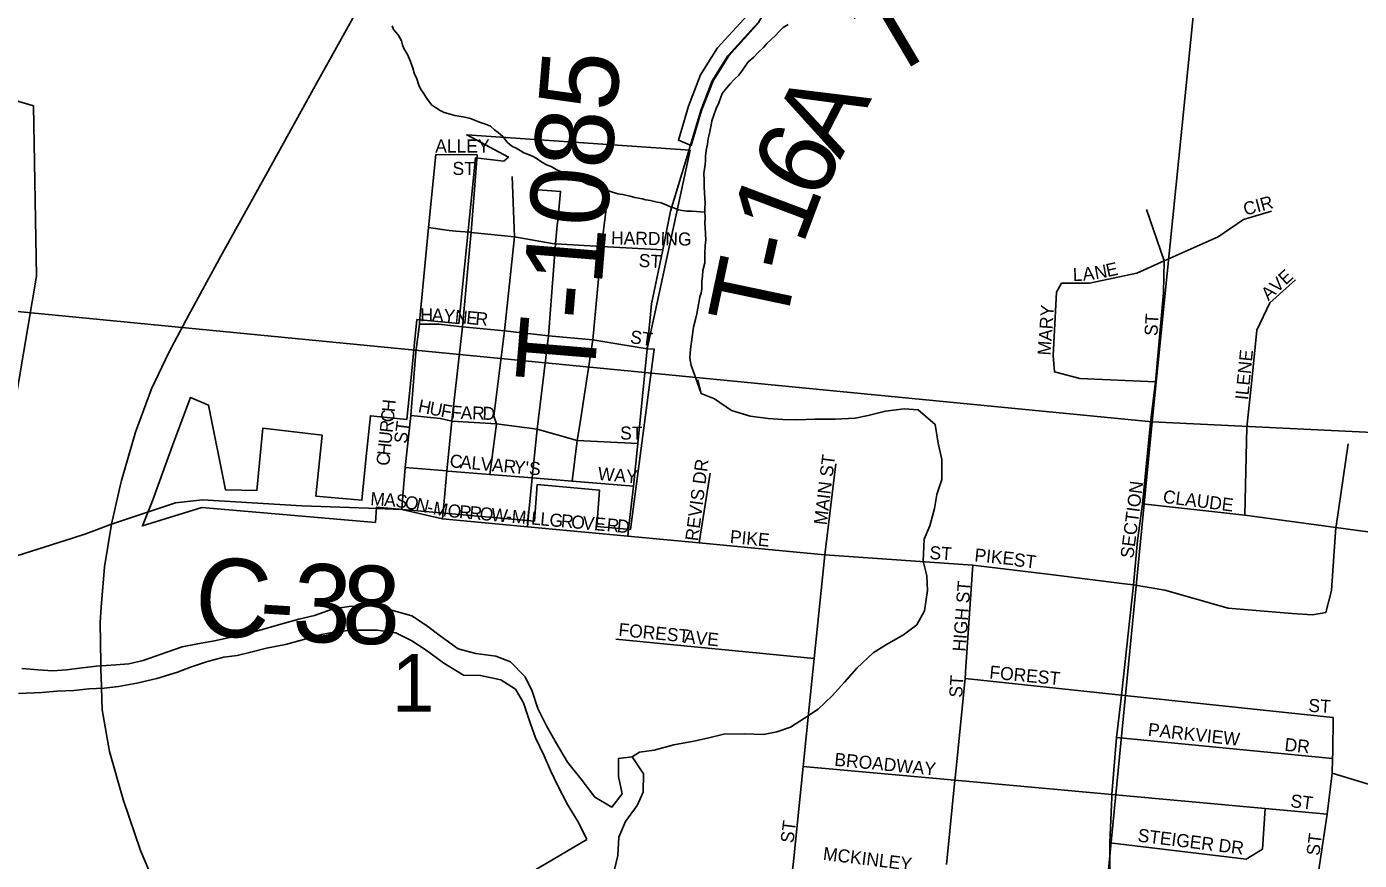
# Model space of a CAD drawing. Extents: x 0 to 34, y -4 to 22.
# Drawn here: x 5.062 to 5.742, y 17.725 to 18.151 of the extents above; entities that cross this region are included whole.
import ezdxf

# ---------------------------------------------------------------- set-up
doc = ezdxf.new("R2010")
doc.units = 0
for name, color, linetype in [('GM_X_City_Street', 7, 'Continuous'), ('GM_X_City_Street_Text', 7, 'Continuous'), ('GM_X_Corporation', 7, 'Continuous'), ('GM_X_County_Road', 7, 'Continuous'), ('GM_X_County_Road_Text', 7, 'Continuous'), ('GM_X_Minor_River', 7, 'Continuous'), ('GM_X_Section', 7, 'Continuous'), ('GM_X_Section_Text', 7, 'Continuous'), ('GM_X_State_Route', 7, 'Continuous'), ('GM_X_Township_Road', 7, 'Continuous'), ('GM_X_Township_Road_Text', 7, 'Continuous'), ('GM_X_Township_ROW', 7, 'Continuous'), ('GM_X_Township_Subdivision', 7, 'Continuous'), ('GM_X_Township_Subdivision_Text', 7, 'Continuous')]:
    doc.layers.add(name, color=color, linetype=linetype)

msp = doc.modelspace()

# ---------------------------------------------------------------- linework, layer by layer
at = {"layer": 'GM_X_City_Street'}
for points in [[(5.27062, 18.0859), (5.29176, 18.08574)], [(5.63136, 17.90479), (5.63174, 17.90741), (5.63574, 17.94878), (5.63841, 17.96979), (5.64241, 18.01517), (5.64275, 18.03151), (5.63374, 18.05787)], [(5.63841, 17.96979), (5.59971, 17.97147), (5.5867, 17.9748), (5.58603, 17.98314), (5.5877, 18.0155), (5.59037, 18.02017), (5.60465, 18.02018), (5.6288, 18.0252), (5.64275, 18.03151), (5.67035, 18.04379), (5.68336, 18.05263), (5.69761, 18.0569)], [(5.26689, 18.04859), (5.27746, 18.04703), (5.28092, 18.04675)], [(5.68508, 17.9467), (5.68512, 17.94811), (5.68778, 17.97213), (5.69012, 17.99615), (5.69679, 18.01016), (5.70981, 18.02184)], [(5.68401, 17.9016), (5.68508, 17.9467)], [(5.73064, 17.89595), (5.73683, 17.9381)], [(5.40523, 17.88742), (5.41078, 17.92313)], [(5.46943, 17.8814), (5.47503, 17.92779)], [(5.25323, 17.90455), (5.25382, 17.91153)], [(5.10485, 17.89711), (5.1182, 17.90151), (5.12485, 17.9037)], [(5.23627, 17.90518), (5.25323, 17.90455), (5.27401, 17.89971), (5.31747, 17.89564), (5.36866, 17.89085)], [(5.27401, 17.89971), (5.27467, 17.90687)], [(5.31747, 17.89564), (5.31822, 17.90326)], [(5.62066, 17.80666), (5.62103, 17.80968), (5.62707, 17.86604), (5.62907, 17.88873), (5.63136, 17.90479)], [(5.63174, 17.90741), (5.68401, 17.9016), (5.73055, 17.89534), (5.77956, 17.88875), (5.82697, 17.88237), (5.87075, 17.87648)], [(5.08493, 17.88989), (5.09184, 17.89207), (5.10485, 17.89711)], [(5.36866, 17.89085), (5.36945, 17.89762)], [(5.62252, 17.86661), (5.62707, 17.86604), (5.64308, 17.86337), (5.67544, 17.85403), (5.70813, 17.85136), (5.71848, 17.85069), (5.72537, 17.85198), (5.72826, 17.86315), (5.72951, 17.88072), (5.73055, 17.89534), (5.73064, 17.89595)], [(4.38714, 17.81483), (4.45287, 17.83314), (4.50971, 17.84877), (4.57933, 17.86961), (4.62669, 17.88287), (4.64942, 17.88287), (4.86174, 17.86416), (4.91107, 17.85815), (4.95215, 17.8548), (4.96722, 17.85635), (4.99636, 17.86184), (5.08493, 17.88989)], [(5.36866, 17.89085), (5.40523, 17.88742), (5.44783, 17.88343)], [(5.44783, 17.88343), (5.46943, 17.8814), (5.545, 17.87605), (5.54484, 17.87376)], [(5.46142, 17.80356), (5.46397, 17.82832), (5.46943, 17.8814)], [(5.54484, 17.87376), (5.54151, 17.8242)], [(5.545, 17.87605), (5.5847, 17.87138), (5.62252, 17.86661)], [(5.36258, 17.83827), (5.46397, 17.82832)], [(5.54151, 17.8242), (5.54111, 17.81819), (5.62103, 17.80968), (5.72564, 17.79855)], [(5.53601, 17.76749), (5.5365, 17.77239), (5.54111, 17.81819)], [(5.61599, 17.75753), (5.61605, 17.75885), (5.61839, 17.78798), (5.62066, 17.80666)], [(5.44097, 17.64142), (5.44324, 17.64787), (5.44562, 17.66039), (5.44744, 17.67536), (5.45259, 17.71772), (5.45331, 17.72468), (5.4583, 17.77321), (5.46142, 17.80356)], [(5.72564, 17.79855), (5.72919, 17.79817), (5.72886, 17.78046)], [(5.61839, 17.78798), (5.7288, 17.77737)], [(5.72886, 17.78046), (5.7288, 17.77737), (5.72865, 17.76986), (5.76503, 17.75881), (5.78948, 17.75139), (5.81441, 17.74382), (5.82715, 17.73996)], [(5.4583, 17.77321), (5.5358, 17.76615)], [(5.53155, 17.72313), (5.5319, 17.7266), (5.53587, 17.76615), (5.53601, 17.76749)], [(5.5358, 17.76615), (5.53587, 17.76615), (5.61605, 17.75885), (5.69429, 17.75172), (5.72603, 17.74883)], [(5.70634, 17.59125), (5.7183, 17.69768), (5.72603, 17.74883), (5.72865, 17.76986)], [(5.61523, 17.70819), (5.61505, 17.73426), (5.61599, 17.75753)], [(5.61505, 17.73426), (5.68463, 17.72584), (5.69303, 17.73102), (5.69429, 17.75172)]]:
    msp.add_lwpolyline(points, dxfattribs=at)
at = {"layer": 'GM_X_Corporation'}
for points in [[(5.42987, 18.15717), (5.41459, 18.14035), (5.40585, 18.12661), (5.39971, 18.11054), (5.39455, 18.09331), (5.40111, 18.09053), (5.40646, 18.10839), (5.41227, 18.1236), (5.42034, 18.13629), (5.43595, 18.15363)], [(5.05329, 17.94512), (5.06658, 18.02376), (5.06502, 18.11083), (4.93029, 18.15055)], [(5.05329, 17.94512), (5.06658, 18.02376), (5.06502, 18.11083), (4.93029, 18.15055)]]:
    msp.add_lwpolyline(points, dxfattribs=at)
msp.add_lwpolyline([(5.23974, 17.89786), (5.24029, 17.90568), (5.32104, 17.89862), (5.32235, 17.91724), (5.35423, 17.91445), (5.35292, 17.89583), (5.37002, 17.89433), (5.38224, 17.98644), (5.37863, 17.98662), (5.40058, 18.08807), (5.28645, 18.09596), (5.30775, 18.08462), (5.30546, 18.08258), (5.29089, 18.0842), (5.2824, 17.99957), (5.26095, 18.0016), (5.26059, 17.99798), (5.25978, 17.98989), (5.25851, 17.97709), (5.25587, 17.95052), (5.2372, 17.95245), (5.23513, 17.93167), (5.23291, 17.90929), (5.2094, 17.91136), (5.21251, 17.9425), (5.18229, 17.9461), (5.17917, 17.91422), (5.16323, 17.91457), (5.15457, 17.95788), (5.14536, 17.9618), (5.13672, 17.93912), (5.12593, 17.9089), (5.12073, 17.89613), (5.15109, 17.90549)], close=True, dxfattribs=at)
at = {"layer": 'GM_X_County_Road'}
msp.add_lwpolyline([(5.12485, 17.9037), (5.13755, 17.90789), (5.15148, 17.9095), (5.20221, 17.90644), (5.23627, 17.90518)], dxfattribs=at)
at = {"layer": 'GM_X_Minor_River'}
for points in [[(5.40805, 18.05647), (5.40164, 18.05694), (5.39896, 18.05702), (5.39656, 18.05736), (5.3947, 18.05769), (5.39258, 18.05855), (5.39046, 18.05915), (5.38861, 18.06001), (5.3857, 18.06117), (5.38304, 18.06179), (5.38039, 18.0624), (5.37799, 18.06274), (5.37613, 18.06334), (5.37427, 18.06366), (5.3724, 18.06398), (5.37001, 18.06459), (5.36602, 18.06552), (5.36362, 18.06586), (5.35991, 18.06704), (5.35699, 18.06793), (5.35381, 18.06883), (5.35117, 18.06998), (5.34851, 18.0706), (5.34508, 18.07231), (5.34165, 18.07375), (5.33743, 18.07602), (5.33426, 18.07718), (5.33215, 18.07832), (5.32952, 18.07973), (5.32714, 18.08061), (5.32425, 18.0823), (5.32242, 18.08369), (5.32031, 18.08483), (5.31794, 18.08597), (5.31556, 18.08684), (5.31372, 18.08797), (5.31161, 18.0891), (5.30951, 18.09024), (5.30716, 18.09218), (5.30485, 18.09519), (5.3025, 18.09713), (5.30067, 18.09852), (5.29859, 18.10046), (5.29594, 18.10134), (5.29303, 18.1025), (5.29038, 18.10338), (5.28827, 18.10425), (5.28455, 18.10516), (5.28242, 18.1055), (5.28028, 18.10583), (5.27789, 18.10644), (5.27497, 18.10733), (5.27287, 18.10846), (5.27103, 18.10959), (5.26841, 18.11127), (5.2661, 18.11455), (5.26432, 18.11728), (5.26278, 18.11946), (5.26204, 18.12135), (5.26083, 18.12513), (5.25982, 18.12703), (5.25885, 18.13), (5.25762, 18.13351), (5.25613, 18.13703), (5.25435, 18.14002), (5.25361, 18.14192), (5.25315, 18.14407), (5.25137, 18.14706), (5.24905, 18.1498), (5.24831, 18.1517)], [(5.40442, 17.97083), (5.4062, 17.96384), (5.40216, 17.97544), (5.40118, 17.97815), (5.4007, 17.98003), (5.4005, 17.98191), (5.40059, 17.98458), (5.40096, 17.98777), (5.40131, 17.99016), (5.40166, 17.99282), (5.40236, 17.99761), (5.40329, 18.00159), (5.40392, 18.00451), (5.40456, 18.00743), (5.40521, 18.01115), (5.40555, 18.01327), (5.40615, 18.01512), (5.40649, 18.01725), (5.40655, 18.01912), (5.40662, 18.02126), (5.40697, 18.02365), (5.40706, 18.02658), (5.408, 18.03056), (5.40808, 18.03296), (5.40816, 18.03536), (5.40829, 18.03937), (5.40866, 18.0423), (5.40849, 18.04524), (5.40833, 18.04872), (5.40813, 18.05059), (5.40822, 18.05353), (5.40805, 18.05647), (5.40813, 18.05887), (5.40819, 18.06074), (5.40802, 18.06369), (5.40784, 18.06636), (5.40768, 18.06957), (5.40779, 18.07278), (5.40763, 18.07625), (5.40798, 18.07865), (5.40832, 18.08077), (5.40839, 18.08291), (5.40846, 18.08504), (5.40883, 18.08797), (5.40947, 18.09116), (5.40983, 18.09408), (5.41045, 18.09674), (5.41078, 18.0986), (5.4114, 18.10098), (5.41174, 18.10311), (5.41264, 18.10602), (5.41382, 18.10946), (5.41526, 18.11235), (5.41614, 18.11473), (5.41702, 18.1171), (5.41842, 18.11893), (5.42094, 18.12206), (5.42316, 18.12439), (5.42537, 18.12646), (5.42733, 18.12907), (5.43015, 18.13326), (5.43317, 18.13557), (5.43512, 18.13792), (5.43816, 18.14076), (5.43983, 18.14258), (5.44204, 18.14465), (5.44426, 18.14672), (5.44592, 18.14854), (5.44814, 18.15087), (5.45061, 18.1524)], [(5.37089, 17.77816), (5.3747, 17.78047), (5.38222, 17.78161), (5.39219, 17.7843), (5.40241, 17.78619), (5.40941, 17.78762), (5.41776, 17.78981), (5.4282, 17.78982), (5.4381, 17.78957), (5.44483, 17.79101), (5.45184, 17.79324), (5.45892, 17.79787), (5.466, 17.80251), (5.47314, 17.80928), (5.47947, 17.81633), (5.48581, 17.82339), (5.49404, 17.83121), (5.50085, 17.83558), (5.50954, 17.84044), (5.51636, 17.84562), (5.52029, 17.85273), (5.5219, 17.86312), (5.52156, 17.87061), (5.51961, 17.87814), (5.52017, 17.88936), (5.52302, 17.89623), (5.52539, 17.90499), (5.52665, 17.91218), (5.52925, 17.91987), (5.52925, 17.93002), (5.52732, 17.93836), (5.5257, 17.94802), (5.51706, 17.95545), (5.50984, 17.9559), (5.50045, 17.9548), (5.49156, 17.95261), (5.48483, 17.95118), (5.47464, 17.95063), (5.4642, 17.95063), (5.45509, 17.95032), (5.44787, 17.9505), (5.44039, 17.95095), (5.43132, 17.95225), (5.42176, 17.95516), (5.41308, 17.96099), (5.4062, 17.96384)], [(5.36191, 17.72064), (5.3637, 17.72782), (5.36421, 17.73716), (5.36763, 17.74509), (5.37346, 17.75323), (5.37658, 17.7601), (5.37682, 17.76945), (5.37089, 17.77816), (5.36391, 17.77726), (5.36394, 17.76817), (5.36585, 17.7593), (5.36059, 17.75249), (5.35189, 17.75751), (5.3449, 17.76678), (5.3379, 17.7755), (5.33226, 17.785), (5.32713, 17.79395), (5.32281, 17.80288), (5.31983, 17.81177), (5.31627, 17.81908), (5.30871, 17.82675), (5.30129, 17.82961), (5.29115, 17.83093), (5.28211, 17.8333), (5.27292, 17.83994), (5.26583, 17.8452), (5.25846, 17.85019), (5.24677, 17.85342), (5.23665, 17.85555), (5.2262, 17.85501), (5.2176, 17.85362), (5.20868, 17.85037), (5.2006, 17.84843), (5.18901, 17.84525), (5.182, 17.84328), (5.17311, 17.84083), (5.16449, 17.83891), (5.15749, 17.83748), (5.14889, 17.83582), (5.14109, 17.83442), (5.13029, 17.83068), (5.1211, 17.82743), (5.11383, 17.82574), (5.10712, 17.82511), (5.09721, 17.82456), (5.08996, 17.82367), (5.0819, 17.82253), (5.07493, 17.82217), (5.06745, 17.82263), (5.05917, 17.82337)], [(5.0575, 17.81058), (5.06929, 17.81109), (5.07707, 17.81169), (5.08564, 17.81202), (5.09343, 17.81289), (5.1012, 17.81323), (5.10845, 17.81412), (5.11786, 17.81575), (5.12809, 17.81817), (5.13861, 17.82138), (5.14537, 17.82389), (5.15401, 17.82688), (5.16236, 17.82907), (5.16908, 17.82998), (5.17608, 17.83167), (5.18416, 17.83361), (5.19384, 17.8355), (5.20247, 17.83796), (5.21218, 17.84066), (5.22132, 17.8423), (5.2307, 17.84287), (5.24061, 17.84289), (5.25021, 17.84158), (5.2584, 17.83736), (5.26577, 17.83264), (5.2747, 17.826), (5.28471, 17.81987), (5.29354, 17.81965), (5.30392, 17.81752), (5.31129, 17.81279), (5.31539, 17.80574), (5.31888, 17.79549), (5.32163, 17.78794), (5.32594, 17.77874), (5.32922, 17.77118), (5.33304, 17.76333), (5.33788, 17.75386), (5.34353, 17.74463), (5.34785, 17.73597)], [(5.34785, 17.73597), (5.3166, 17.7175)]]:
    msp.add_lwpolyline(points, dxfattribs=at)
at = {"layer": 'GM_X_Section'}
for points in [[(4.99815, 18.79148), (5.71418, 18.71571), (5.63665, 17.94928), (4.91493, 18.01957), (4.99198, 18.73294)], [(5.71418, 18.71571), (6.41744, 18.64125), (6.34502, 17.8912), (5.93259, 17.93493), (5.63665, 17.94928)]]:
    msp.add_lwpolyline(points, close=True, dxfattribs=at)
for points in [[(4.91493, 18.01957), (5.63665, 17.94928), (5.59773, 17.55115)], [(5.74889, 17.46593), (5.74176, 17.46953), (5.7262, 17.47835), (5.7175, 17.48358), (5.70722, 17.48991), (5.69853, 17.4954), (5.68796, 17.50094), (5.68165, 17.50532), (5.6727, 17.51162), (5.66481, 17.51763), (5.66113, 17.52037), (5.65481, 17.52422), (5.6498, 17.52725), (5.64479, 17.53054), (5.63951, 17.53277), (5.63583, 17.53604), (5.62711, 17.5402), (5.61892, 17.54409), (5.6078, 17.54803), (5.59773, 17.55115), (5.63665, 17.94928), (5.93259, 17.93493)]]:
    msp.add_lwpolyline(points, dxfattribs=at)
at = {"layer": 'GM_X_State_Route'}
for points in [[(5.10816, 17.9113), (5.10957, 17.91737), (5.11004, 17.9194), (5.11718, 17.94404), (5.12533, 17.96612), (5.13424, 17.98481), (5.14432, 18.00357), (5.16083, 18.03394), (5.18293, 18.07381), (5.2081, 18.11949), (5.23243, 18.16332), (5.25786, 18.2082), (5.28523, 18.2565), (5.3195, 18.31729), (5.32527, 18.32738), (5.32693, 18.33028), (5.34144, 18.35564), (5.35424, 18.37795)], [(5.09958, 17.81925), (5.09947, 17.82246), (5.09941, 17.82604), (5.09911, 17.84679), (5.0997, 17.85463), (5.10128, 17.87531), (5.10485, 17.89711), (5.10816, 17.9113)], [(5.14871, 17.66455), (5.14582, 17.67087), (5.13523, 17.69402), (5.133, 17.69889), (5.11976, 17.73025), (5.1109, 17.75642), (5.10387, 17.78093), (5.1002, 17.80214), (5.09958, 17.81925)]]:
    msp.add_lwpolyline(points, dxfattribs=at)
at = {"layer": 'GM_X_Township_Road'}
for points in [[(5.3963, 18.07596), (5.39765, 18.08045), (5.40603, 18.10839), (5.41184, 18.1236), (5.41991, 18.1363), (5.4352, 18.15312), (5.43561, 18.15377), (5.43933, 18.15967)], [(5.28835, 18.04275), (5.28865, 18.0461), (5.29176, 18.08574)], [(5.38572, 18.03314), (5.38656, 18.03727), (5.3906, 18.05692), (5.3963, 18.07596)], [(5.27878, 17.9498), (5.2843, 17.99792), (5.28835, 18.04275)], [(5.36945, 17.89762), (5.37165, 17.91643), (5.37391, 17.9383), (5.37863, 17.98662), (5.38087, 18.00953), (5.38572, 18.03314)], [(5.27467, 17.90687), (5.27627, 17.92423), (5.27877, 17.94971), (5.27878, 17.9498)]]:
    msp.add_lwpolyline(points, dxfattribs=at)
at = {"layer": 'GM_X_Township_ROW'}
for points in [[(5.26252, 18.0022), (5.26689, 18.04859), (5.27062, 18.0859)], [(5.3107, 18.04827), (5.30969, 18.07465)], [(5.34034, 17.91899), (5.34293, 17.93982), (5.344, 17.94679)], [(5.25504, 17.92596), (5.27627, 17.92423), (5.27691, 17.92418)]]:
    msp.add_lwpolyline(points, dxfattribs=at)
at = {"layer": 'GM_X_Township_Subdivision'}
for points in [[(5.3325, 18.04798), (5.33308, 18.05385), (5.33438, 18.06704), (5.32295, 18.0679)], [(5.344, 17.94679), (5.35083, 17.99123), (5.35525, 18.03895), (5.35763, 18.05811)], [(5.28092, 18.04675), (5.28798, 18.04616)], [(5.28798, 18.04616), (5.28865, 18.0461), (5.3091, 18.04396)], [(5.30575, 17.99574), (5.31088, 18.04377), (5.3107, 18.04827)], [(5.3091, 18.04396), (5.31088, 18.04377), (5.33004, 18.0405)], [(5.31822, 17.90326), (5.31993, 17.92066), (5.3224, 17.94563), (5.32814, 17.99326), (5.33174, 18.04021), (5.3325, 18.04798)], [(5.33004, 18.0405), (5.33174, 18.04021), (5.35525, 18.03895), (5.38656, 18.03727)], [(5.25382, 17.91153), (5.25504, 17.92596), (5.25788, 17.95253), (5.26036, 17.98486), (5.26223, 17.99916), (5.26252, 18.0022)], [(5.26223, 17.99916), (5.27218, 17.99916), (5.28414, 17.99793)], [(5.28414, 17.99793), (5.2843, 17.99792), (5.30575, 17.99574), (5.32814, 17.99326), (5.35083, 17.99123), (5.35696, 17.99022)], [(5.29826, 17.92243), (5.30171, 17.94833), (5.3003, 17.95221), (5.30575, 17.99574)], [(5.35696, 17.99022), (5.37863, 17.98662)], [(5.25788, 17.95253), (5.27295, 17.95098), (5.27877, 17.94971), (5.30171, 17.94833), (5.3224, 17.94563), (5.34293, 17.93982), (5.37391, 17.9383)], [(5.27691, 17.92418), (5.29826, 17.92243), (5.31993, 17.92066), (5.34034, 17.91899), (5.37165, 17.91643)]]:
    msp.add_lwpolyline(points, dxfattribs=at)

# ---------------------------------------------------------------- texts
at = {"layer": 'GM_X_City_Street_Text'}
for s, height, rotation, p in [('ALLEY', 0.006667, 0.00001, (5.27035, 18.08692)), ('ST', 0.006667, 0.00001, (5.27915, 18.07545)), ('CIR', 0.006667, 15.2568, (5.68421, 18.05461)), ('E', 0.00667, 12.52966, (5.61383, 18.02326)), ('L', 0.00667, 2.08828, (5.59622, 18.02122)), ('A', 0.00667, 6.26483, (5.60144, 18.02143)), ('N', 0.00667, 10.44139, (5.6078, 18.02215)), ('AVE', 0.006667, 42.27517, (5.69601, 18.01092)), ('MARY', 0.006667, 86.01119, (5.58473, 17.98309)), ('ST', 0.006667, 86.42621, (5.63929, 17.99305)), ('ILENE', 0.006667, 84.28723, (5.68564, 17.96025)), ('REVIS DR', 0.006667, 82.64426, (5.40463, 17.88813)), ('MAIN ST', 0.006667, 82.99866, (5.47034, 17.89633)), ('SECTION', 0.006667, 82.5255, (5.62697, 17.87931)), ('M', 0.00667, 355.80666, (5.237, 17.90682)), ('A', 0.00667, 355.82651, (5.24402, 17.9063)), ('S', 0.00667, 353.20715, (5.24979, 17.90588)), ('O', 0.00667, 348.15861, (5.2543, 17.90535)), ('N', 0.00667, 347.1938, (5.26001, 17.90415)), ('M', 0.00667, 349.30827, (5.26886, 17.90215)), ('CLAUDE', 0.006667, 352.74688, (5.64187, 17.90798)), ('-', 0.00667, 347.26718, (5.26574, 17.90285)), ('O', 0.00667, 354.62071, (5.27644, 17.90075)), ('R', 0.00667, 354.86395, (5.28231, 17.9002)), ('R', 0.00667, 354.86933, (5.28757, 17.89972)), ('O', 0.00667, 354.86791, (5.29283, 17.89925)), ('W', 0.00667, 354.86494, (5.29868, 17.89873)), ('-', 0.00667, 354.85226, (5.30627, 17.89805)), ('M', 0.00667, 354.85528, (5.30919, 17.89778)), ('I', 0.00667, 354.87117, (5.31621, 17.89715)), ('L', 0.00667, 354.85751, (5.31913, 17.89689)), ('L', 0.00667, 354.87058, (5.3238, 17.89647)), ('G', 0.00667, 354.85702, (5.32848, 17.89605)), ('R', 0.00667, 354.86395, (5.33432, 17.89553)), ('O', 0.00667, 354.87879, (5.33958, 17.89505)), ('V', 0.00667, 354.85702, (5.34542, 17.89453)), ('E', 0.00667, 354.86036, (5.35126, 17.894)), ('R', 0.00667, 354.86933, (5.3577, 17.89343)), ('D', 0.00667, 354.85702, (5.36296, 17.89295)), ('PIKE', 0.006667, 354.47516, (5.42066, 17.88745)), ('ST', 0.006667, 356.42537, (5.5227, 17.87924)), ('PIKE', 0.006667, 354.28508, (5.54562, 17.87806)), ('ST', 0.006667, 352.87835, (5.5656, 17.87571)), ('HIGH ST', 0.006667, 85.76166, (5.54132, 17.83174)), ('FOREST', 0.006667, 354.51048, (5.36375, 17.83993)), ('AVE', 0.006667, 354.08949, (5.3972, 17.83641)), ('ST', 0.006667, 86.41175, (5.53955, 17.80825)), ('FOREST', 0.006667, 354.50631, (5.55325, 17.81823)), ('ST', 0.006667, 356.42537, (5.7163, 17.80121)), ('PARKVIEW', 0.006667, 353.74658, (5.63422, 17.78889)), ('DR', 0.006667, 353.99339, (5.70403, 17.78126)), ('BROADWAY', 0.006667, 354.35995, (5.47405, 17.77364)), ('ST', 0.006667, 352.88003, (5.70699, 17.75252)), ('ST', 0.006667, 82.86488, (5.45332, 17.73383)), ('STEIGER DR', 0.006667, 352.87364, (5.62896, 17.73492)), ('ST', 0.006667, 82.86488, (5.72201, 17.72737)), ('MCKINLEY', 0.006667, 352.97229, (5.46821, 17.72553))]:
    msp.add_text(s, height=height, rotation=rotation, dxfattribs=at).set_placement(p)
at = {"layer": 'GM_X_County_Road_Text'}
for s, rotation, p in [('C', 355.49922, (5.14624, 17.84099)), ('3', 357.46108, (5.19688, 17.8373)), ('8', 358.48836, (5.22228, 17.83618)), ('-', 356.45456, (5.17972, 17.83836))]:
    msp.add_text(s, height=0.04, rotation=rotation, dxfattribs=at).set_placement(p)
at = {"layer": 'GM_X_Section_Text'}
msp.add_text('1', height=0.02944, rotation=0.00001, dxfattribs=at).set_placement((5.24806, 17.80118))
at = {"layer": 'GM_X_Township_Road_Text'}
for s, rotation, p in [('T', 30.61243, (5.50158, 18.12385)), ('T-1085', 85.2916, (5.35124, 17.96809)), ('A', 62.72789, (5.47723, 18.08292)), ('6', 63.30461, (5.46621, 18.061)), ('1', 69.37086, (5.45797, 18.03897)), ('-', 77.42546, (5.45482, 18.02436)), ('T', 78.095, (5.44868, 17.9952))]:
    msp.add_text(s, height=0.04, rotation=rotation, dxfattribs=at).set_placement(p)
at = {"layer": 'GM_X_Township_Subdivision_Text'}
for s, height, rotation, p in [('HARDING', 0.006667, 359.10189, (5.36013, 18.03999)), ('ST', 0.006667, 356.41176, (5.37414, 18.02854)), ('H', 0.00667, 359.86884, (5.26272, 18.00068)), ('A', 0.00667, 357.94523, (5.26853, 18.00067)), ('Y', 0.00667, 354.85702, (5.2743, 18.00047)), ('N', 0.00667, 354.6809, (5.28013, 17.99994)), ('E', 0.00667, 354.69363, (5.28598, 17.9994)), ('R', 0.00667, 354.68568, (5.29065, 17.99896)), ('ST', 0.006667, 352.88003, (5.36965, 17.98953)), ('H', 0.00667, 84.16839, (5.2496, 17.95406)), ('H', 0.00667, 348.7801, (5.26122, 17.95432)), ('U', 0.00667, 348.79268, (5.26697, 17.95317)), ('F', 0.00667, 349.62949, (5.27283, 17.95202)), ('F', 0.00667, 355.72051, (5.27822, 17.95107)), ('A', 0.00667, 358.41648, (5.28324, 17.95071)), ('R', 0.00667, 358.47377, (5.28911, 17.95055)), ('D', 0.00667, 358.49524, (5.29439, 17.9504)), ('R', 0.00667, 84.16132, (5.24853, 17.94355)), ('C', 0.00667, 84.16132, (5.24906, 17.9488)), ('ST', 0.006667, 82.86488, (5.25586, 17.93795)), ('U', 0.00667, 84.17632, (5.24793, 17.93771)), ('ST', 0.006667, 0.00001, (5.36481, 17.94026)), ('H', 0.00667, 84.18042, (5.24734, 17.93188)), ('C', 0.00667, 84.16132, (5.2468, 17.92662)), ('C', 0.00667, 354.57693, (5.27752, 17.92617)), ('A', 0.00667, 354.58629, (5.28277, 17.92567)), ('L', 0.00667, 354.58298, (5.28861, 17.92512)), ('V', 0.00667, 354.5721, (5.29329, 17.92468)), ('A', 0.00667, 354.58629, (5.29913, 17.92412)), ('R', 0.00667, 354.57693, (5.30497, 17.92357)), ('Y', 0.00667, 354.57578, (5.31023, 17.92307)), ("'", 0.00667, 354.60174, (5.31607, 17.92252)), ('S', 0.00667, 356.97385, (5.31812, 17.92233)), ('WAY', 0.006667, 354.64735, (5.35319, 17.91972))]:
    msp.add_text(s, height=height, rotation=rotation, dxfattribs=at).set_placement(p)

doc.saveas('drawing.dxf')
